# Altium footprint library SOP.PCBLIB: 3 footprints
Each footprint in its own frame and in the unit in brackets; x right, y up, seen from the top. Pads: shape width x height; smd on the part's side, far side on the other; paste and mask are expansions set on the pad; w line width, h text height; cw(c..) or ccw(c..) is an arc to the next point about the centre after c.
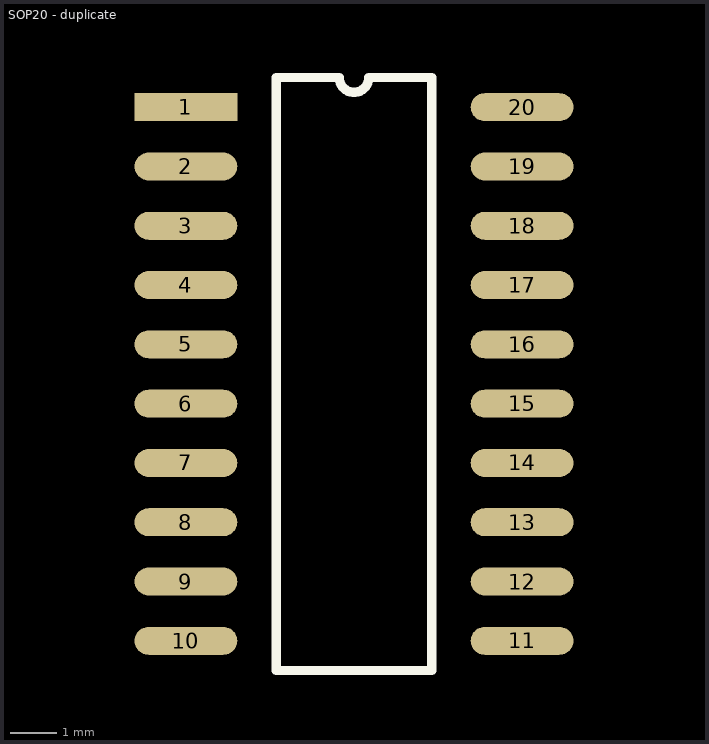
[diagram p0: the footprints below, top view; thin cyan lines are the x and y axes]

## PCBComponent_1 [mm]

## SOP20 [mm]

## SOP20 - duplicate [mm]
pads (20):
  rect 2.2x0.6 smd: 1(-508,458.216)
  oval 2.2x0.6 smd: 2(-508,456.946) 3(-508,455.676) 4(-508,454.406) 5(-508,453.136) 6(-508,451.866) 7(-508,450.596) 8(-508,449.326) 9(-508,448.056) 10(-508,446.786) 11(-500.8,446.786) 12(-500.8,448.056) 13(-500.8,449.326) 14(-500.8,450.596) 15(-500.8,451.866) 16(-500.8,453.136) 17(-500.8,454.406) 18(-500.8,455.676) 19(-500.8,456.946) 20(-500.8,458.216)
Top Overlay:
  lines w0.2: -506.065,446.151 -506.065,458.851 -504.717,458.851 ccw(c-504.4,458.851) -504.082,458.851 -502.735,458.851 -502.735,446.151 -506.065,446.151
